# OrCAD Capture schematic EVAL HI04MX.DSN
size A; title: EVAL HI04MX; rev: A4; note: 1
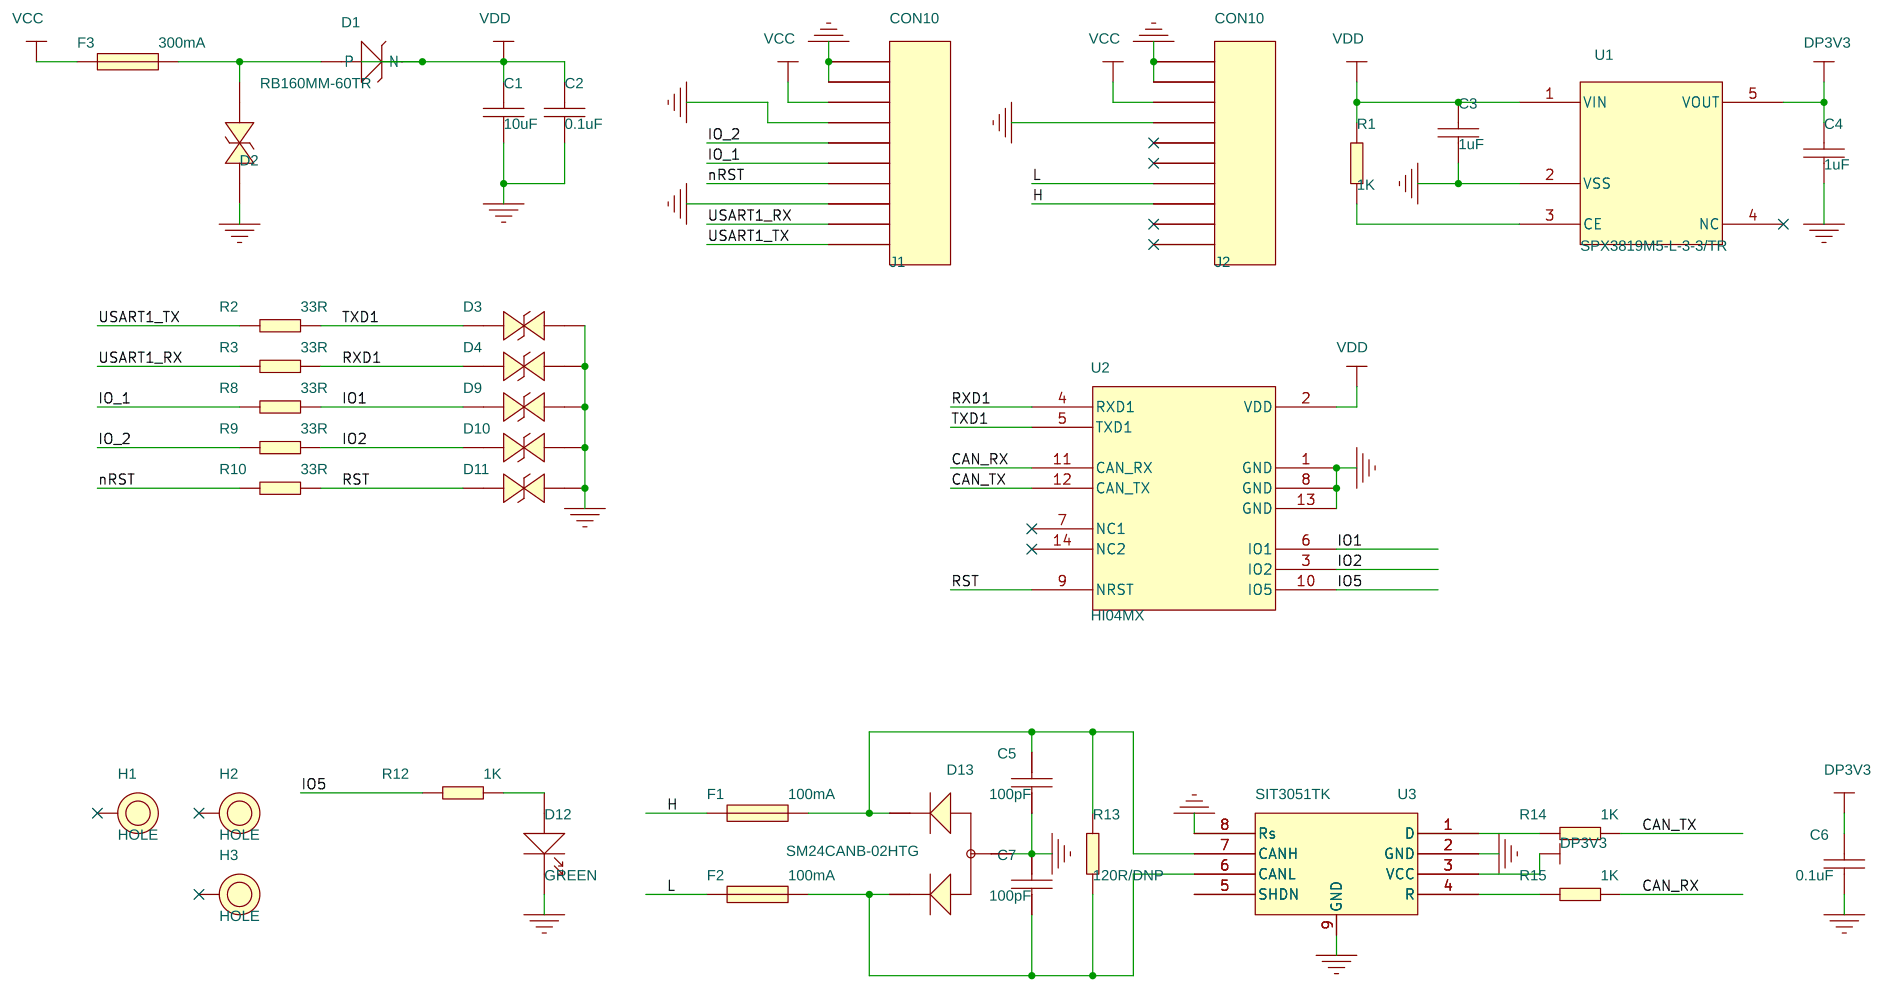
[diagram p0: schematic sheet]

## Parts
C1  10uF  [C0603]
C2  0.1uF  [C0402]
C3  1uF  [C0402]
C4  1uF  [C0402]
C5  100pF  [C0402]
C6  0.1uF  [C0402]
C7  100pF  [C0402]
D1  RB160MM-60TR  [SOD123FL]
D2  SDD32A05L01  [DO-214AC]
D3  SBD52C05L01  [SOD-523]
D4  SBD52C05L01  [SOD-523]
D9  SBD52C05L01  [SOD-523]
D10  SBD52C05L01  [SOD-523]
D11  SBD52C05L01  [SOD-523]
D12  GREEN  [LED0402]
D13  SM24CANB-02HTG  [SOT23-3-0_95]
F1  100mA  [F0603]
F2  100mA  [F0603]
F3  300mA  [F0603]
H1  HOLE  [HOLE-2-MM]
H2  HOLE  [HOLE-2-MM]
H3  HOLE  [HOLE-2-MM]
J1  CON10  [5015680807_1]
J2  CON10  [5015680807_1]
R1  1K  [R0402]
R2  33R  [R0402]
R3  33R  [R0402]
R8  33R  [R0402]
R9  33R  [R0402]
R10  33R  [R0402]
R12  1K  [R0402]
R13  120R/DNP  [R0805]
R14  1K  [R0402]
R15  1K  [R0402]
U1  SPX3819M5-L-3-3/TR  [SOT23-5-0_95]
U2  HI04MX  [HI03_HI04MX]
U3  SIT3051TK  [HVSON8]

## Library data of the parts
C1-C7 = Capacity_Nonpolarity
D1 = diode
D2-D4 D9-D11 = DIODE_BI-DIR_TRIG
D12 = LED
D13 = BAT54A_SOT
F1-F3 = Fuse
H1-H3 = HOLE
J1 J2 = CON10
R1-R3 R8-R10 R12-R15 = Res
U1 = XC6210
U2 = HI04MX
U3 = SIT3051TK

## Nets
GND: C1.1 C2.1 C3.2 C4.1 C5.2 C6.2 C7.1 D2.1 D3.1 D4.1 D9.1 D10.1 D11.1 D12.2(-) D13.3 J1.3 J1.7 J1.9 J1.10 J2.7 J2.9 J2.10 U1.2(VSS) U2.1(GND) U2.8(GND) U2.13(GND) U3.2(GND) U3.8(Rs) U3.9(GND)
VCC: F3.1 J1.8 J2.8
VDD: C1.2 C2.2 C3.1 D1.2(N) R1.2 U1.1(VIN) U2.2(VDD)
CAN_RX: R15.1 U2.11(CAN_RX)
CAN_TX: R14.1 U2.12(CAN_TX)
DP3V3: C4.2 C6.1 U1.5(VOUT) U3.3(VCC)
H: F1.1 J2.3
IO1: D9.2 R8.1 U2.6(IO1)
IO2: D10.2 R9.1 U2.3(IO2)
IO5: R12.1 U2.10(IO5)
IO_1: J1.5 R8.2
IO_2: J1.6 R9.2
L: F2.1 J2.4
nRST: J1.4 R10.2
RST: D11.2 R10.1 U2.9(NRST)
RXD1: D4.2 R3.1 U2.4(RXD1)
TXD1: D3.2 R2.1 U2.5(TXD1)
USART1_RX: J1.2 R3.2
USART1_TX: J1.1 R2.2
N2198535: D12.1(+) R12.2
N2224750: R1.1 U1.3(CE)
N2242059: C5.1 D13.1 F1.2 R13.2 U3.7(CANH)
N2242241: R14.2 U3.1(D)
N2242331: C7.2 D13.2 F2.2 R13.1 U3.6(CANL)
N2242381: R15.2 U3.4(R)
N2269430: D1.1(P) D2.2 F3.2

Not connected (* = marked no-connect by the designer): H1 1*; H2 1*; H3 1*; J2 1* 2* 5* 6*; U1 4(NC)*; U2 7(NC1)* 14(NC2)*; U3 5(SHDN)
